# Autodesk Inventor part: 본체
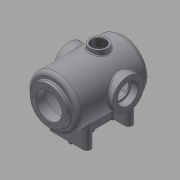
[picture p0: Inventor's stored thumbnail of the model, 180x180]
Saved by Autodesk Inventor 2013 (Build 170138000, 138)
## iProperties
Created: 2016-02
Part Number: 본체
Material: 알루미늄 6061
Document SubType Name: Modeling
Designer: mduedu
Density: 2.71 g/cm^3
Author: mduedu
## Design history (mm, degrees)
sketch "스케치2"
  geometry: L1 (0, 100)-(0, -100); L2 (65, -75.993)-(65, 100); L3 (65, 100)-(0, 100); A1 r 100 centre (0, 0) between (0, -100) and (65, -75.993); 2 further points
  constraints: 6 end point, 2 midpoint, 2 point on circle, 1 centre point, 1 coincident, 1 horizontal, 1 parallel, 1 vertical
  dimensions: "d3" = 200 distance of L1.start L1.end; "d5" = 130 diameter of L2 L1; "d6" = 100 radius of A1
revolve "회전1" sketch "스케치2" stored, may be unused: angle "d7" = 90 deg
sketch "스케치3"
  geometry: C1 r 47.5 at (0, 0); 1 further point
  constraints: 1 centre point, 1 coincident
  dimensions: "d8" = 95 diameter of C1
extrude "돌출2" join sketch "스케치3" distance "d10" = 10; taper "d11" = 0 deg
sketch "스케치5"
  geometry: L1 (47.5, 110)-(47.5, 100) reference; L2 (47.5, 100)-(65, 100) reference; L3 (65, 100)-(65, -75.993) reference; L4 (-65, -75.993)-(-65, 100) reference; L5 (-65, 100)-(-47.5, 100) reference; L6 (-47.5, 100)-(-47.5, 110) reference; L7 (-47.5, 110)-(47.5, 110) reference; L8 (55, 85)-(55, -71.239); L9 (0, 85)-(55, 85); L10 (0, 85)-(0, -90); A1 r 100 centre (0, 0) between (0, -100) and (65, -75.993) reference; A2 r 100 centre (0, 0) between (-65, -75.993) and (0, -100) reference; A3 r 90 centre (0, 0) between (0, -90) and (55, -71.239); 1 further point
  constraints: 6 end point, 2 point on circle, 1 centre point, 1 parallel, 1 perpendicular, 1 point on line, 1 vertical
  dimensions: "d13" = 10 distance between parallel lines of L3 L8; "d14" = 10 radial gap between concentric circles of A3 A1; "d15" = 15 distance between parallel lines of L9 L2
revolve "회전2" sketch "스케치5" stored, may be unused: angle "d16" = 90 deg
hole "구멍1" diameter "d19" = 65; stored, may be unused: countersink angle "d23" = 90 deg, drill point angle "d25" = 118 deg; dims "d17" = 10, "d18" = 10, "d20" = 6, "d21" = 4, "d22" = 2, "d24" = 8
node "작업 평면1"
sketch "스케치6"
  geometry: L1 (47.5, 110)-(-47.5, 110) reference; C1 r 40 at (0, -17); 1 further point
  constraints: 1 centre point, 1 vertical alignment
  dimensions: "d27" = 80 diameter of C1; "d29" = 127 distance from line of C1.centre L1
extrude "돌출3" join sketch "스케치6" stored distance "d30" = 10; taper "d31" = 0 deg
hole "구멍2" diameter "d34" = 42; stored, may be unused: countersink angle "d38" = 90 deg, drill point angle "d40" = 118 deg; dims "d32" = 10, "d33" = 10, "d35" = 6, "d36" = 52, "d37" = 18, "d39" = 8
sketch "스케치7" dims "d41" = 65
  geometry: C1 r 40 at (0, 0) reference; 3 further points
  constraints: 2 vertical alignment, 1 coincident, 2 other
hole "구멍3" sketch "스케치7" at (0, 32.5) diameter "d43" = 3.242; stored, may be unused: countersink angle "d47" = 90 deg, drill point angle "d49" = 118 deg; dims "d44" = 11, "d45" = 13, "d46" = 18, "d48" = 13
sketch "스케치8" dims "d53" = 80
  geometry: 3 further points
  constraints: 2 vertical alignment, 1 coincident, 2 other
hole "구멍4" sketch "스케치8" at (0, 40) diameter "d56" = 3.242; stored, may be unused: countersink angle "d60" = 90 deg, drill point angle "d62" = 118 deg; dims "d57" = 11, "d58" = 13, "d59" = 18, "d61" = 13
fillet "모깎기1" dims "d66" = 10
fillet "모깎기2" dims "d67" = 3
fillet "모깎기3" dims "d68" = 0.3
chamfer "모따기1" distance "d69" = 1; stored, may be unused: second distance "d70" = 2, angle "d71" = 45 deg
node "작업 평면5"
sketch "스케치10"
  geometry: L1 (-50, -63)-(50, -63); L2 (50, -63)-(50, -43); L3 (50, -43)-(-50, -43); L4 (-50, -43)-(-50, -63); L5 (-50, 0)-(50, 0); L6 (-50, 63)-(50, 63); L7 (50, 63)-(50, 43); L8 (50, 43)-(-50, 43); L9 (-50, 43)-(-50, 63); 2 further points
  constraints: 18 end point, 4 symmetric about line, 2 parallel, 2 perpendicular, 1 coincident, 1 horizontal, 1 midpoint
  dimensions: "d80" = 20 distance of L3.end L1.start; "d82" = 100 distance of L1.start L1.end; "d130" = 43 vertical distance of L3.end point (0, 0); "d131" = 50 horizontal distance of L3.end point (0, 0); "d132" = 100 distance of L5.start L5.end
extrude "돌출5" join sketch "스케치10" stored distance "d84" = 10; taper "d85" = 0 deg
sketch "스케치11"
  geometry: L1 (-100, -43)-(-100, 43); L2 (-65, 90)-(-65, -71.239) reference; L3 (-100, -43)-(-41.533, -43) reference; L4 (-100, 43)-(-41.533, 43) reference; 1 further point
  constraints: 2 end point, 1 point on line, 1 vertical
feature "리브1" sketch "스케치11" dims "d88" = 1, "d89" = 20, "d90" = 0, "d91" = 0, "d92" = 1, "d93" = 1
fillet "모깎기12"
fillet "모깎기13"
fillet "모깎기14"
fillet "모깎기15"
fillet "모깎기16" dims "d167" = 3
fillet "모깎기17" dims "d168" = 3
node "작업 평면6"
sketch "스케치19"
  geometry: L1 (75, -57)-(75, 23) reference; L2 (-75, -57)-(-75, 23) reference; L3 (75, -17)-(-75, -17); C1 r 22.5 at (0, -17); 1 further point
  constraints: 3 midpoint, 2 end point, 1 centre point
  dimensions: "d149" = 45 diameter of C1
extrude "돌출11" join sketch "스케치19" stored distance "d150" = 10; taper "d151" = 0 deg
hole "구멍6" diameter "d154" = 35; stored, may be unused: countersink angle "d158" = 90 deg, drill point angle "d160" = 118 deg; dims "d152" = 10, "d153" = 10, "d155" = 6, "d156" = 4, "d157" = 2, "d159" = 8
fillet "모깎기11" dims "d161" = 3
feature "스레드1" dims "d162" = 10, "d163" = 0
chamfer "모따기3" distance "d164" = 1; stored, may be unused: second distance "d165" = 2, angle "d166" = 45 deg
sketch "스케치20"
  geometry: L1 (10, 40)-(10, -40) reference; L2 (13, -43)-(40, -43) reference; L3 (40, -63)-(-40, -63) reference; L4 (-40, -43)-(-13, -43) reference; L5 (-10, -40)-(-10, 40) reference; L6 (-13, 43)-(-40, 43) reference; L7 (-40, 63)-(40, 63) reference; L8 (40, 43)-(13, 43) reference; L9 (-40, 53)-(40, 53); L10 (-40, -53)-(40, -53); L11 (0, 53)-(0, -53); C1 r 5 at (0, 53); C2 r 5 at (0, 0); C3 r 5 at (0, -53); A1 r 3 centre (13, -40) between (10, -40) and (13, -43) reference; A2 r 10 centre (40, -53) between (40, -63) and (40, -43) reference; A3 r 10 centre (-40, -53) between (-40, -43) and (-40, -63) reference; A4 r 3 centre (-13, -40) between (-13, -43) and (-10, -40) reference; A5 r 3 centre (-13, 40) between (-10, 40) and (-13, 43) reference; A6 r 10 centre (-40, 53) between (-40, 63) and (-40, 43) reference; A7 r 10 centre (40, 53) between (40, 43) and (40, 63) reference; A8 r 3 centre (13, 40) between (13, 43) and (10, 40) reference; 1 further point
  constraints: 6 end point, 3 centre point, 3 coincident, 2 midpoint, 2 parallel
  dimensions: "d169" = 10 diameter of C1; "d170" = 10 diameter of C2; "d171" = 10 diameter of C3
extrude "돌출12" join sketch "스케치20" distance "d172" = 10; taper "d173" = 0 deg
chamfer "모따기4" distance "d174" = 1; stored, may be unused: second distance "d175" = 2, angle "d176" = 45 deg
node "솔리드2"
pattern_circular "원형 패턴1" dims angle "d51" = 360 deg
mirror "대칭1"
pattern_circular "원형 패턴2" dims angle "d64" = 360 deg
node "절단 모서리 투영1"
node "절단 모서리 투영4"
other parameters: "d26" = 75, "d136" = 175
